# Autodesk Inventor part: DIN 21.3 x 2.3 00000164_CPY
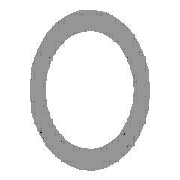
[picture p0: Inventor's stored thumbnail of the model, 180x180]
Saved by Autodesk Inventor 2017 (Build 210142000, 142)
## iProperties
Created: 2017-11
Part Number: DIN 21.3 x 2.3 00000164_CPY
Material: Steel, Mild
Description: Pipe
Document SubType Name: Modeling
Standard: DIN
Designer: iusti
Standard Revision: 2006-07
Standards Organization: DIN
Language: en-US
Size Designation: 21.3 x 2.3
Categories: <MemberInstance><Categories><Category DisplayName="Structural Shapes" InternalName="089c4875-fa83-4c05-b084-43b9cc11f5ed" Mnemonic="GRDR"><CategoryParameter Dis
Stock Number: 21.3 x 2.3
Density: 7.85 g/cm^3
Appearance: Semi-Polished
IsCustomPart: 1
G_L: 500.000 mm
G_W: 21.300 mm
G_H: 21.300 mm
_CCFamilyMember: 1
_CCFamilyDisplayName: DIN EN 10210-2 - Pipe
_FrameMemberDoc: Frame Member File
_Version: 15.0.0
_GetPNFromCC: 1
Author: iusti
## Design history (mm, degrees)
node "Start plane"
node "End plane"
sketch "Sketch"
  geometry: C1 r 8.35 at (0, 0); C2 r 10.65 at (0, 0); 2 further points
  constraints: 3 coincident, 2 centre point
  dimensions: "d0" = 21.3 diameter of C2 (= G_H); "d1" = 2.3 radial gap between concentric circles of C2 C1 (= G_T)
extrude "Body" new body sketch "Sketch" stored distance "d2" = 500 (= G_L); taper "d3" = 0 deg
node "Driven Length"
  sketch "Sketch3"
    geometry: L1 (0, 0)-(10, 0) reference
    constraints: 2 end point, 1 horizontal
  workplane "Work Plane3"
  sketch "Sketch4"
    geometry: L1 (-2, 0)-(12, 0) reference; L2 (-2, 500)-(12, 500) reference
    dimensions: "d7" = 500 distance between parallel lines of L1 L2 (derived)
body "Solid1"
other parameters: "G_H" = 21.3 [user parameter; used in 1 equation term], "G_T" = 2.3 [user parameter; used in 1 equation term], "G_L" = 500 (= d7) [user parameter; used in 1 equation term], "G_OFFSET_START" = 0 [user parameter; used in 1 equation term], "G_OFFSET_END" = 0 [user parameter; used in 1 equation term], "d4" = 0 (computed from G_OFFSET_START), "d6" = 90 deg
